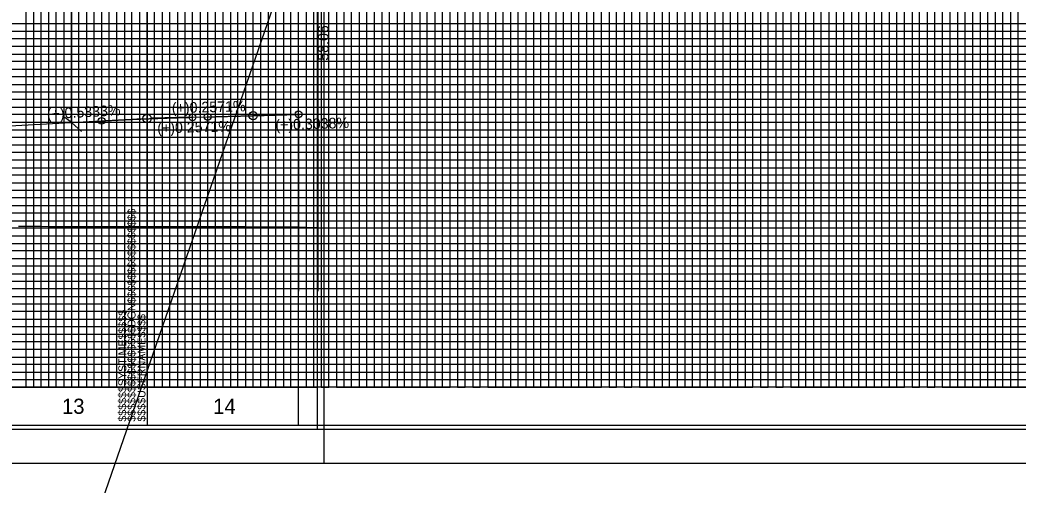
# Model space of a CAD drawing. Extents: x 2345490 to 2445302, y 465165 to 573888.
# Drawn here: x 2412161 to 2412820, y 514167 to 514474 of the extents above; entities that cross this region are included whole.
import ezdxf

# ---------------------------------------------------------------- set-up
doc = ezdxf.new("R2010")
doc.units = 0
for name, color, linetype in [('Old_Level_1', 7, 'Continuous'), ('Old_Level_18', 7, 'Continuous'), ('Old_Level_2', 7, 'Continuous'), ('Old_Level_40', 7, 'Continuous'), ('Old_Level_41', 7, 'Continuous'), ('Old_Level_42', 7, 'Continuous'), ('Old_Level_43', 7, 'Continuous'), ('Old_Level_50', 7, 'Continuous'), ('Old_Level_51', 7, 'Continuous'), ('Old_Level_63', 7, 'Continuous')]:
    doc.layers.add(name, color=color, linetype=linetype)

msp = doc.modelspace()

# ---------------------------------------------------------------- linework, layer by layer
at = {"layer": 'Old_Level_1'}
msp.add_lwpolyline([(2412160.325, 514337.64125), (2412165.325, 514337.60025), (2412170.325, 514337.56075), (2412175.325, 514337.52325), (2412180.325, 514337.467), (2412185.325, 514337.4385), (2412190.325, 514337.4175), (2412195.325, 514337.40325), (2412200.325, 514337.3895), (2412205.325, 514337.37575), (2412210.325, 514337.36225), (2412215.325, 514337.349), (2412220.325, 514337.336), (2412225.325, 514337.30825), (2412230.325, 514337.31225), (2412235.325, 514337.32), (2412240.325, 514337.328), (2412245.325, 514337.3365), (2412250.325, 514337.34525), (2412255.325, 514337.35425), (2412260.325, 514337.3635), (2412265.325, 514337.395), (2412270.325, 514337.42675), (2412275.325, 514337.41625), (2412280.325, 514337.40575), (2412285.325, 514337.39525), (2412290.325, 514337.38475), (2412295.325, 514337.3745), (2412300.325, 514337.364), (2412305.325, 514337.3325), (2412310.325, 514337.29775), (2412315.325, 514337.26325), (2412320.325, 514337.2285), (2412325.325, 514337.194), (2412330.325, 514337.186), (2412335.325, 514337.20325), (2412340.325, 514337.22075), (2412345.325, 514337.08875), (2412350.325, 514336.932), (2412355.325, 514336.775), (2412358.115, 514336.69)], dxfattribs=at)
at = {"layer": 'Old_Level_18'}
msp.add_line((2412245.325, 514206.21425), (2412245.325, 514206.21425), dxfattribs=at)
msp.add_line((2412245.325, 514206.21425), (2412245.325, 514206.21425), dxfattribs=at)
for points in [[(2412345.325, 515256.21425), (2410845.325, 515256.21425), (2410845.325, 514206.21425), (2412345.325, 514206.21425)], [(2413745.325, 515256.21425), (2412245.325, 515256.21425), (2412245.325, 514206.21425), (2413745.325, 514206.21425)]]:
    msp.add_lwpolyline(points, close=True, dxfattribs=at)
at = {"layer": 'Old_Level_2'}
for p, q in [((2406888.2485, 498751.813), (2414623.19775, 521117.51825)), ((2412358.115, 514630.7145), (2412358.115, 514411.8145)), ((2412285.325, 514409.74325), (2412312.576, 514410.444)), ((2412345.325, 514411.426), (2412318.07375, 514410.59825)), ((2412345.325, 514411.426), (2412358.115, 514411.8145)), ((2411965.325, 514393.78125), (2412215.325, 514407.1145)), ((2412215.325, 514407.1145), (2412242.579, 514408.56825)), ((2412275.325, 514409.486), (2412248.07425, 514408.78525)), ((2412275.325, 514409.486), (2412285.325, 514409.74325))]:
    msp.add_line(p, q, dxfattribs=at)
for centre, radius in [((2412245.325, 514408.7145), 2.75), ((2412275.325, 514409.486), 2.25), ((2412285.325, 514409.74325), 2.25), ((2412315.325, 514410.5145), 2.75), ((2412345.325, 514411.426), 2.25), ((2412215.325, 514407.1145), 2.25)]:
    msp.add_circle(centre, radius, dxfattribs=at)
for points in [[(2412285.325, 514409.74325), (2412286.525, 514409.774), (2412287.725, 514409.80525), (2412288.925, 514409.83625), (2412290.125, 514409.8675), (2412291.325, 514409.899), (2412292.525, 514409.93025), (2412293.725, 514409.962), (2412294.925, 514409.99375), (2412296.125, 514410.0255), (2412297.325, 514410.05725), (2412298.525, 514410.0895), (2412299.725, 514410.1215), (2412300.925, 514410.15375), (2412302.125, 514410.18625), (2412303.325, 514410.21875), (2412304.525, 514410.25125), (2412305.725, 514410.284), (2412306.925, 514410.31675), (2412308.125, 514410.34975), (2412309.325, 514410.38275), (2412310.525, 514410.416), (2412311.725, 514410.44925), (2412312.925, 514410.4825), (2412314.125, 514410.516), (2412315.325, 514410.5495), (2412316.525, 514410.58325), (2412317.725, 514410.61725), (2412318.925, 514410.651), (2412320.125, 514410.68525), (2412321.325, 514410.71925), (2412322.525, 514410.7535), (2412323.725, 514410.788), (2412324.925, 514410.8225), (2412326.125, 514410.857), (2412327.325, 514410.89175), (2412328.525, 514410.92675), (2412329.725, 514410.9615), (2412330.925, 514410.99675), (2412332.125, 514411.03175), (2412333.325, 514411.067), (2412334.525, 514411.1025), (2412335.725, 514411.138), (2412336.925, 514411.1735), (2412338.125, 514411.20925), (2412339.325, 514411.24525), (2412340.525, 514411.281), (2412341.725, 514411.31725), (2412342.925, 514411.35325), (2412344.125, 514411.38975), (2412345.325, 514411.426)], [(2412215.325, 514407.1145), (2412216.525, 514407.17825), (2412217.725, 514407.24125), (2412218.925, 514407.30375), (2412220.125, 514407.36525), (2412221.325, 514407.42625), (2412222.525, 514407.48675), (2412223.725, 514407.5465), (2412224.925, 514407.6055), (2412226.125, 514407.66375), (2412227.325, 514407.7215), (2412228.525, 514407.7785), (2412229.725, 514407.835), (2412230.925, 514407.8905), (2412232.125, 514407.94575), (2412233.325, 514408), (2412234.525, 514408.05375), (2412235.725, 514408.10675), (2412236.925, 514408.15925), (2412238.125, 514408.211), (2412239.325, 514408.262), (2412240.525, 514408.3125), (2412241.725, 514408.36225), (2412242.925, 514408.41125), (2412244.125, 514408.45975), (2412245.325, 514408.5075), (2412246.525, 514408.5545), (2412247.725, 514408.601), (2412248.925, 514408.64675), (2412250.125, 514408.692), (2412251.325, 514408.73625), (2412252.525, 514408.78), (2412253.725, 514408.82325), (2412254.925, 514408.86575), (2412256.125, 514408.9075), (2412257.325, 514408.9485), (2412258.525, 514408.989), (2412259.725, 514409.029), (2412260.925, 514409.068), (2412262.125, 514409.1065), (2412263.325, 514409.14425), (2412264.525, 514409.1815), (2412265.725, 514409.218), (2412266.925, 514409.25375), (2412268.125, 514409.289), (2412269.325, 514409.3235), (2412270.525, 514409.35725), (2412271.725, 514409.3905), (2412272.925, 514409.423), (2412274.125, 514409.45475), (2412275.325, 514409.486)]]:
    msp.add_spline(points, degree=3, dxfattribs=at)
at = {"layer": 'Old_Level_40'}
msp.add_line((2412245.325, 514206.21425), (2412245.325, 514206.21425), dxfattribs=at)
msp.add_line((2412245.325, 514206.21425), (2412245.325, 514206.21425), dxfattribs=at)
msp.add_line((2412245.325, 514206.21425), (2412245.325, 514206.21425), dxfattribs=at)
msp.add_line((2412245.325, 514206.21425), (2412245.325, 514206.21425), dxfattribs=at)
at = {"layer": 'Old_Level_41'}
for p, q in [((2412345.325, 514231.21425), (2410845.325, 514231.21425)), ((2413745.325, 514231.21425), (2412245.325, 514231.21425))]:
    msp.add_line(p, q, dxfattribs=at)
for points in [[(2412245.325, 515256.21425), (2412295.325, 515256.21425), (2412295.325, 514231.21425), (2412345.325, 514231.21425), (2412345.325, 515256.21425), (2412395.325, 515256.21425), (2412395.325, 514231.21425), (2412445.325, 514231.21425), (2412445.325, 515256.21425), (2412495.325, 515256.21425), (2412495.325, 514231.21425), (2412545.325, 514231.21425), (2412545.325, 515256.21425), (2412595.325, 515256.21425), (2412595.325, 514231.21425), (2412645.325, 514231.21425), (2412645.325, 515256.21425), (2412695.325, 515256.21425), (2412695.325, 514231.21425), (2412745.325, 514231.21425), (2412745.325, 515256.21425), (2412795.325, 515256.21425), (2412795.325, 514231.21425), (2412845.325, 514231.21425)], [(2412320.325, 514231.21425), (2412320.325, 515256.21425), (2412370.325, 515256.21425), (2412370.325, 514231.21425), (2412420.325, 514231.21425), (2412420.325, 515256.21425), (2412470.325, 515256.21425), (2412470.325, 514231.21425), (2412520.325, 514231.21425), (2412520.325, 515256.21425), (2412570.325, 515256.21425), (2412570.325, 514231.21425), (2412620.325, 514231.21425), (2412620.325, 515256.21425), (2412670.325, 515256.21425), (2412670.325, 514231.21425), (2412720.325, 514231.21425), (2412720.325, 515256.21425), (2412770.325, 515256.21425), (2412770.325, 514231.21425), (2412820.325, 514231.21425), (2412820.325, 515256.21425), (2412870.325, 515256.21425)], [(2412170.325, 515118.66425), (2412170.325, 514231.21425), (2412220.325, 514231.21425), (2412220.325, 515118.66425)], [(2412270.325, 515118.66425), (2412270.325, 514231.21425)], [(2412345.325, 514456.21425), (2410845.325, 514456.21425), (2410845.325, 514406.21425), (2412345.325, 514406.21425)], [(2413745.325, 514456.21425), (2412245.325, 514456.21425), (2412245.325, 514406.21425), (2413745.325, 514406.21425)], [(2412345.325, 514356.21425), (2410845.325, 514356.21425), (2410845.325, 514306.21425), (2412345.325, 514306.21425)], [(2413745.325, 514356.21425), (2412245.325, 514356.21425), (2412245.325, 514306.21425), (2413745.325, 514306.21425)], [(2412345.325, 514281.21425), (2410845.325, 514281.21425), (2410845.325, 514331.21425), (2412345.325, 514331.21425)], [(2413745.325, 514281.21425), (2412245.325, 514281.21425), (2412245.325, 514331.21425), (2413745.325, 514331.21425)], [(2412345.325, 514256.21425), (2410845.325, 514256.21425)], [(2413745.325, 514256.21425), (2412245.325, 514256.21425)], [(2412282.825, 514206.21425), (2412282.825, 514206.21425)]]:
    msp.add_lwpolyline(points, dxfattribs=at)
at = {"layer": 'Old_Level_42'}
for points in [[(2412195.325, 515118.66425), (2412195.325, 514231.21425), (2412245.325, 514231.21425), (2412245.325, 515118.66425)], [(2412295.325, 515118.66425), (2412295.325, 514231.21425), (2412345.325, 514231.21425)], [(2412345.325, 514381.21425), (2410845.325, 514381.21425), (2410845.325, 514431.21425), (2412345.325, 514431.21425)], [(2413745.325, 514381.21425), (2412245.325, 514381.21425), (2412245.325, 514431.21425), (2413745.325, 514431.21425)]]:
    msp.add_lwpolyline(points, dxfattribs=at)
at = {"layer": 'Old_Level_43'}
for points in [[(2412300.325, 515256.21425), (2412300.325, 514231.21425), (2412305.325, 514231.21425), (2412305.325, 515256.21425)], [(2412310.325, 515256.21425), (2412310.325, 514231.21425), (2412315.325, 514231.21425), (2412315.325, 515256.21425)], [(2412325.325, 515256.21425), (2412325.325, 514231.21425), (2412330.325, 514231.21425), (2412330.325, 515256.21425)], [(2412335.325, 515256.21425), (2412335.325, 514231.21425), (2412340.325, 514231.21425), (2412340.325, 515256.21425)], [(2412350.325, 515256.21425), (2412350.325, 514231.21425), (2412355.325, 514231.21425), (2412355.325, 515256.21425)], [(2412360.325, 515256.21425), (2412360.325, 514231.21425), (2412365.325, 514231.21425), (2412365.325, 515256.21425)], [(2412375.325, 515256.21425), (2412375.325, 514231.21425), (2412380.325, 514231.21425), (2412380.325, 515256.21425)], [(2412385.325, 515256.21425), (2412385.325, 514231.21425), (2412390.325, 514231.21425), (2412390.325, 515256.21425)], [(2412400.325, 515256.21425), (2412400.325, 514231.21425), (2412405.325, 514231.21425), (2412405.325, 515256.21425)], [(2412410.325, 515256.21425), (2412410.325, 514231.21425), (2412415.325, 514231.21425), (2412415.325, 515256.21425)], [(2412425.325, 515256.21425), (2412425.325, 514231.21425), (2412430.325, 514231.21425), (2412430.325, 515256.21425)], [(2412435.325, 515256.21425), (2412435.325, 514231.21425), (2412440.325, 514231.21425), (2412440.325, 515256.21425)], [(2412450.325, 515256.21425), (2412450.325, 514231.21425), (2412455.325, 514231.21425), (2412455.325, 515256.21425)], [(2412460.325, 514231.21425), (2412465.325, 514231.21425), (2412465.325, 515256.21425)], [(2412460.325, 515256.21425), (2412460.325, 514231.21425)], [(2412475.325, 515256.21425), (2412475.325, 514231.21425), (2412480.325, 514231.21425), (2412480.325, 515256.21425)], [(2412485.325, 515256.21425), (2412485.325, 514231.21425), (2412490.325, 514231.21425), (2412490.325, 515256.21425)], [(2412500.325, 515256.21425), (2412500.325, 514231.21425), (2412505.325, 514231.21425), (2412505.325, 515256.21425)], [(2412510.325, 515256.21425), (2412510.325, 514231.21425), (2412515.325, 514231.21425), (2412515.325, 515256.21425)], [(2412525.325, 515256.21425), (2412525.325, 514231.21425), (2412530.325, 514231.21425), (2412530.325, 515256.21425)], [(2412535.325, 515256.21425), (2412535.325, 514231.21425), (2412540.325, 514231.21425), (2412540.325, 515256.21425)], [(2412550.325, 515256.21425), (2412550.325, 514231.21425), (2412555.325, 514231.21425), (2412555.325, 515256.21425)], [(2412560.325, 515256.21425), (2412560.325, 514231.21425), (2412565.325, 514231.21425), (2412565.325, 515256.21425)], [(2412575.325, 515256.21425), (2412575.325, 514231.21425), (2412580.325, 514231.21425), (2412580.325, 515256.21425)], [(2412585.325, 515256.21425), (2412585.325, 514231.21425), (2412590.325, 514231.21425), (2412590.325, 515256.21425)], [(2412600.325, 515256.21425), (2412600.325, 514231.21425), (2412605.325, 514231.21425), (2412605.325, 515256.21425)], [(2412610.325, 515256.21425), (2412610.325, 514231.21425), (2412615.325, 514231.21425), (2412615.325, 515256.21425)], [(2412625.325, 515256.21425), (2412625.325, 514231.21425), (2412640.325, 514231.21425), (2412640.325, 515256.21425)], [(2412630.325, 515256.21425), (2412630.325, 514231.21425), (2412635.325, 514231.21425), (2412635.325, 515256.21425)], [(2412630.325, 515255.61425), (2412630.325, 514231.21425), (2412635.325, 514231.21425), (2412635.325, 515255.61425)], [(2412650.325, 515256.21425), (2412650.325, 514231.21425), (2412655.325, 514231.21425), (2412655.325, 515256.21425)], [(2412660.325, 515256.21425), (2412660.325, 514231.21425), (2412665.325, 514231.21425), (2412665.325, 515256.21425)], [(2412675.325, 515256.21425), (2412675.325, 514231.21425), (2412680.325, 514231.21425), (2412680.325, 515256.21425)], [(2412685.325, 515256.21425), (2412685.325, 514231.21425), (2412690.325, 514231.21425), (2412690.325, 515256.21425)], [(2412700.325, 515256.21425), (2412700.325, 514231.21425), (2412705.325, 514231.21425), (2412705.325, 515256.21425)], [(2412710.325, 515256.21425), (2412710.325, 514231.21425), (2412715.325, 514231.21425), (2412715.325, 515256.21425)], [(2412725.325, 515256.21425), (2412725.325, 514231.21425), (2412730.325, 514231.21425), (2412730.325, 515256.21425)], [(2412735.325, 515256.21425), (2412735.325, 514231.21425), (2412740.325, 514231.21425), (2412740.325, 515256.21425)], [(2412750.325, 515256.21425), (2412750.325, 514231.21425), (2412755.325, 514231.21425), (2412755.325, 515256.21425)], [(2412760.325, 515256.21425), (2412760.325, 514231.21425), (2412765.325, 514231.21425), (2412765.325, 515256.21425)], [(2412775.325, 515256.21425), (2412775.325, 514231.21425)], [(2412780.325, 515256.21425), (2412780.325, 514231.21425), (2412785.325, 514231.21425), (2412785.325, 515256.21425), (2412790.325, 515256.21425), (2412790.325, 514231.21425), (2412800.325, 514231.21425), (2412800.325, 515256.21425), (2412805.325, 515256.21425), (2412805.325, 514231.21425), (2412810.325, 514231.21425), (2412810.325, 515256.21425), (2412815.325, 515256.21425), (2412815.325, 514231.21425)], [(2412165.325, 515118.66425), (2412165.325, 514231.21425), (2412175.325, 514231.21425), (2412175.325, 515118.66425)], [(2412180.325, 515118.66425), (2412180.325, 514231.21425), (2412185.325, 514231.21425), (2412185.325, 515118.66425)], [(2412190.325, 515118.66425), (2412190.325, 514231.21425), (2412200.325, 514231.21425), (2412200.325, 515118.66425)], [(2412205.325, 515118.66425), (2412205.325, 514231.21425), (2412210.325, 514231.21425), (2412210.325, 515118.66425)], [(2412215.325, 515118.66425), (2412215.325, 514231.21425), (2412225.325, 514231.21425), (2412225.325, 515118.66425)], [(2412230.325, 515118.66425), (2412230.325, 514231.21425)], [(2412230.325, 514231.21425), (2412235.325, 514231.21425), (2412235.325, 515118.66425)], [(2412240.325, 515118.66425), (2412240.325, 514231.21425), (2412250.325, 514231.21425), (2412250.325, 515118.66425)], [(2412255.325, 515118.66425), (2412255.325, 514231.21425), (2412260.325, 514231.21425), (2412260.325, 515118.66425)], [(2412265.325, 515118.66425), (2412265.325, 514231.21425), (2412275.325, 514231.21425), (2412275.325, 515118.66425)], [(2412280.325, 515118.66425), (2412280.325, 514231.21425), (2412285.325, 514231.21425), (2412285.325, 515118.66425)], [(2412290.325, 515118.66425), (2412290.325, 514231.21425), (2412300.325, 514231.21425)], [(2412295.325, 514471.21425), (2410895.325, 514471.21425), (2410895.325, 514466.21425), (2412295.325, 514466.21425)], [(2413695.325, 514471.21425), (2412295.325, 514471.21425), (2412295.325, 514466.21425), (2413695.325, 514466.21425)], [(2412295.325, 514461.21425), (2410895.325, 514461.21425), (2410895.325, 514451.21425), (2412295.325, 514451.21425)], [(2413695.325, 514461.21425), (2412295.325, 514461.21425), (2412295.325, 514451.21425), (2413695.325, 514451.21425)], [(2412295.325, 514446.21425), (2410895.325, 514446.21425), (2410895.325, 514441.21425), (2412295.325, 514441.21425)], [(2413695.325, 514446.21425), (2412295.325, 514446.21425), (2412295.325, 514441.21425), (2413695.325, 514441.21425)], [(2412295.325, 514436.21425), (2410895.325, 514436.21425)], [(2413695.325, 514436.21425), (2412295.325, 514436.21425)], [(2410895.325, 514426.21425), (2412295.325, 514426.21425)], [(2412295.325, 514426.21425), (2413695.325, 514426.21425)], [(2412295.325, 514421.21425), (2410895.325, 514421.21425), (2410895.325, 514416.21425), (2412295.325, 514416.21425)], [(2413695.325, 514421.21425), (2412295.325, 514421.21425), (2412295.325, 514416.21425), (2413695.325, 514416.21425)], [(2412295.325, 514411.21425), (2410895.325, 514411.21425)], [(2413695.325, 514411.21425), (2412295.325, 514411.21425)], [(2410895.325, 514401.21425), (2412295.325, 514401.21425)], [(2412295.325, 514401.21425), (2413695.325, 514401.21425)], [(2412295.325, 514396.21425), (2410895.325, 514396.21425), (2410895.325, 514391.21425), (2412295.325, 514391.21425)], [(2413695.325, 514396.21425), (2412295.325, 514396.21425), (2412295.325, 514391.21425), (2413695.325, 514391.21425)], [(2412295.325, 514386.21425), (2410895.325, 514386.21425), (2410895.325, 514376.21425), (2412295.325, 514376.21425)], [(2413695.325, 514386.21425), (2412295.325, 514386.21425), (2412295.325, 514376.21425), (2413695.325, 514376.21425)], [(2412295.325, 514371.21425), (2410895.325, 514371.21425), (2410895.325, 514366.21425), (2412295.325, 514366.21425)], [(2413695.325, 514371.21425), (2412295.325, 514371.21425), (2412295.325, 514366.21425), (2413695.325, 514366.21425)], [(2412295.325, 514361.21425), (2410895.325, 514361.21425), (2410895.325, 514351.21425), (2412295.325, 514351.21425)], [(2413695.325, 514361.21425), (2412295.325, 514361.21425), (2412295.325, 514351.21425), (2413695.325, 514351.21425)], [(2412295.325, 514346.21425), (2410895.325, 514346.21425), (2410895.325, 514341.21425), (2412295.325, 514341.21425)], [(2413695.325, 514346.21425), (2412295.325, 514346.21425), (2412295.325, 514341.21425), (2413695.325, 514341.21425)], [(2412295.325, 514336.21425), (2410895.325, 514336.21425), (2410895.325, 514326.21425), (2412295.325, 514326.21425)], [(2413695.325, 514336.21425), (2412295.325, 514336.21425), (2412295.325, 514326.21425), (2413695.325, 514326.21425)], [(2412295.325, 514321.21425), (2410895.325, 514321.21425), (2410895.325, 514316.21425), (2412295.325, 514316.21425)], [(2413695.325, 514321.21425), (2412295.325, 514321.21425), (2412295.325, 514316.21425), (2413695.325, 514316.21425)], [(2412295.325, 514311.21425), (2410895.325, 514311.21425), (2410895.325, 514301.21425), (2412295.325, 514301.21425)], [(2413695.325, 514311.21425), (2412295.325, 514311.21425), (2412295.325, 514301.21425), (2413695.325, 514301.21425)], [(2412295.325, 514296.21425), (2410895.325, 514296.21425), (2410895.325, 514291.21425), (2412295.325, 514291.21425)], [(2413695.325, 514296.21425), (2412295.325, 514296.21425), (2412295.325, 514291.21425), (2413695.325, 514291.21425)], [(2412295.325, 514286.21425), (2410895.325, 514286.21425), (2410895.325, 514276.21425), (2412295.325, 514276.21425)], [(2413695.325, 514286.21425), (2412295.325, 514286.21425), (2412295.325, 514276.21425), (2413695.325, 514276.21425)], [(2412295.325, 514271.21425), (2410895.325, 514271.21425), (2410895.325, 514266.21425), (2412295.325, 514266.21425)], [(2413695.325, 514271.21425), (2412295.325, 514271.21425), (2412295.325, 514266.21425), (2413695.325, 514266.21425)], [(2412295.325, 514261.21425), (2410895.325, 514261.21425), (2410895.325, 514251.21425), (2412295.325, 514251.21425)], [(2413695.325, 514261.21425), (2412295.325, 514261.21425), (2412295.325, 514251.21425), (2413695.325, 514251.21425)], [(2412295.325, 514246.21425), (2410895.325, 514246.21425), (2410895.325, 514241.21425), (2412295.325, 514241.21425)], [(2413695.325, 514246.21425), (2412295.325, 514246.21425), (2412295.325, 514241.21425), (2413695.325, 514241.21425)], [(2412295.325, 514236.21425), (2410895.325, 514236.21425)], [(2413695.325, 514236.21425), (2412295.325, 514236.21425)]]:
    msp.add_lwpolyline(points, dxfattribs=at)
at = {"layer": 'Old_Level_50'}
for points in [[(2412357.825, 515258.76425), (2410691.325, 515258.76425), (2410691.325, 514203.66425), (2412357.825, 514203.66425)], [(2413757.825, 515258.76425), (2412091.325, 515258.76425), (2412091.325, 514203.66425), (2413757.825, 514203.66425)]]:
    msp.add_lwpolyline(points, close=True, dxfattribs=at)
at = {"layer": 'Old_Level_51'}
for points in [[(2412362.325, 515281.21425), (2410678.325, 515281.21425), (2410678.325, 514181.21425), (2412362.325, 514181.21425)], [(2413762.325, 515281.21425), (2412078.325, 515281.21425), (2412078.325, 514181.21425), (2413762.325, 514181.21425)]]:
    msp.add_lwpolyline(points, close=True, dxfattribs=at)
at = {"layer": 'Old_Level_63'}
for p, q in [((2412195.325, 514406.13425), (2412195.325, 514633.70475)), ((2412345.325, 514411.42425), (2412345.325, 514294.632)), ((2412358.115, 514411.81425), (2412358.115, 514294.632)), ((2412195.325, 514406.13425), (2412191.08425, 514409.392)), ((2412195.325, 514405.93425), (2412195.325, 514294.632)), ((2412195.325, 514405.93425), (2412202.01425, 514399.9935)), ((2412245.325, 514408.51425), (2412245.325, 514294.632)), ((2412295.325, 514410.00425), (2412295.325, 514294.632)), ((2410895.325, 514231.21425), (2412358.114, 514231.21425))]:
    msp.add_line(p, q, dxfattribs=at)

# ---------------------------------------------------------------- texts
at = {"layer": 'Old_Level_1'}
for s, p in [('13', (2412189.131, 514213.7145)), ('14', (2412288.9735, 514213.7145))]:
    msp.add_text(s, height=10.000001, dxfattribs=at).set_placement(p)
at = {"layer": 'Old_Level_2'}
for s, rotation, p in [('58.06', 90, (2412365.115, 514446.8145)), ('(+)0.5333%', 3.05288333, (2412179.35975, 514408.20075)), ('(+)0.2571%', 1.47299444, (2412261.76575, 514412.1385)), ('(+)0.2571%', 1.47299444, (2412252.12625, 514398.88625)), ('(+)0.3038%', 1.74016389, (2412330.108, 514400.95925))]:
    msp.add_text(s, height=7.000001, rotation=rotation, dxfattribs=at).set_placement(p)
at = {"layer": 'Old_Level_41'}
for s, p in [('$$$$$$$$$$$$$$$$DGN$$$$$$$$$$$$$$$$', (2412237.675, 514208.57675)), ('$$$$$$SYSTIME$$$$$', (2412231.625, 514208.57675)), ('$$$$USERNAME$$$$', (2412244.25, 514208.58925))]:
    msp.add_text(s, height=5.25, rotation=90, dxfattribs=at).set_placement(p)

doc.saveas('drawing.dxf')
